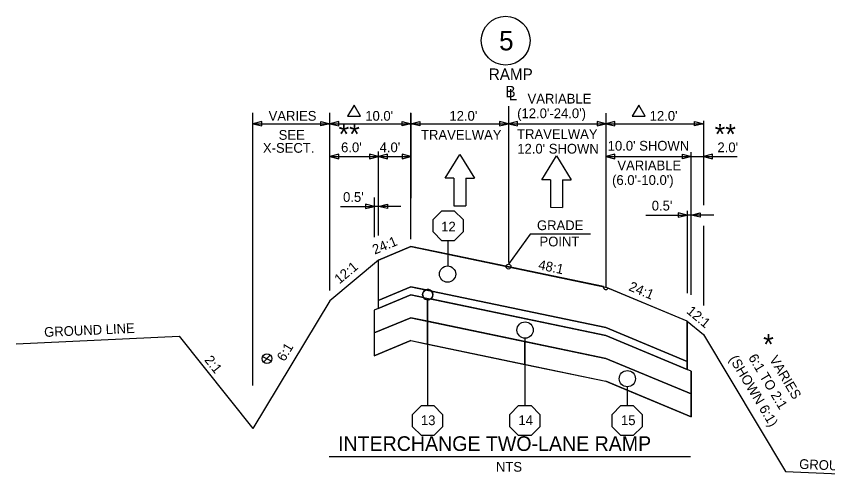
# Model space of a CAD drawing. Extents: x 4932 to 5887, y 4809 to 5473.
# Drawn here: x 5128.5 to 5228.3, y 4886.7 to 4943.3 of the extents above; entities that cross this region are included whole.
import ezdxf

# ---------------------------------------------------------------- set-up
doc = ezdxf.new("R2010")
doc.units = 0
for name, color, linetype in [('Level 2', 7, 'Continuous'), ('Level 20', 7, 'Continuous'), ('Level 25', 7, 'Continuous'), ('RD_QTY_Miscl_1', 7, 'Continuous'), ('RD_QTY_Miscl_2', 7, 'Continuous'), ('RD_QTY_Miscl_3', 7, 'Continuous'), ('RD_QTY_Miscl_4', 7, 'Continuous'), ('RD_SHT_Typical', 7, 'Continuous'), ('RD_TX_TypSect', 7, 'Continuous'), ('RD_XS_ExGround', 7, 'Continuous'), ('typical_on', 7, 'Continuous')]:
    doc.layers.add(name, color=color, linetype=linetype)

msp = doc.modelspace()

# ---------------------------------------------------------------- linework, layer by layer
at = {"layer": 'Level 2'}
for p, q in [((5173.043, 4910.319), (5173.043, 4910.319)), ((5173.043, 4910.264), (5173.043, 4910.264))]:
    msp.add_line(p, q, dxfattribs=at)
at = {"layer": 'Level 20'}
for p, q in [((5181.259, 4923.398), (5183.081, 4926.313)), ((5183.081, 4926.313), (5184.865, 4923.389)), ((5193.153, 4923.198), (5194.975, 4926.112)), ((5194.975, 4926.112), (5196.759, 4923.188)), ((5182.352, 4923.398), (5181.259, 4923.398)), ((5182.352, 4923.398), (5182.352, 4919.997)), ((5183.808, 4923.389), (5184.865, 4923.389)), ((5183.808, 4923.389), (5183.808, 4919.989)), ((5194.245, 4923.198), (5193.153, 4923.198)), ((5194.245, 4923.198), (5194.245, 4919.797)), ((5195.702, 4923.188), (5196.759, 4923.188)), ((5195.702, 4923.188), (5195.702, 4919.788)), ((5182.352, 4919.997), (5183.808, 4919.989)), ((5194.245, 4919.797), (5195.702, 4919.788))]:
    msp.add_line(p, q, dxfattribs=at)
at = {"layer": 'Level 25'}
for p, q in [((5191.736, 4916.499), (5189.068, 4912.805)), ((5199.132, 4916.499), (5191.736, 4916.499))]:
    msp.add_line(p, q, dxfattribs=at)
msp.add_circle((5188.709, 4940.304), 3, dxfattribs=at)
at = {"layer": 'RD_QTY_Miscl_1'}
for p, q in [((5177.064, 4914.978), (5173.065, 4913.312)), ((5173.043, 4913.293), (5173.043, 4908.338)), ((5173.043, 4908.338), (5177.064, 4910.013)), ((5177.064, 4910.013), (5178.885, 4909.634)), ((5211.051, 4905.801), (5201.325, 4909.853)), ((5179.587, 4909.488), (5201.054, 4905.015)), ((5211.052, 4900.85), (5211.051, 4905.801)), ((5201.054, 4905.015), (5211.052, 4900.85))]:
    msp.add_line(p, q, dxfattribs=at)
for points in [[(5200.759, 4910.042), (5181.633, 4914.026), (5177.064, 4914.978)], [(5173.065, 4913.312), (5173.048, 4913.297), (5173.043, 4913.293)]]:
    msp.add_lwpolyline(points, dxfattribs=at)
msp.add_circle((5181.563, 4911.58), 1, dxfattribs=at)
for centre, radius, start, end in [((5201.053, 4909.98), 0.3, 168.23191, 334.96624), ((5179.13, 4909.054), 0.63, 43.52941, 112.93441)]:
    msp.add_arc(centre, radius, start, end, dxfattribs=at)
at = {"layer": 'RD_QTY_Miscl_2'}
for p, q in [((5177.064, 4910.013), (5173.043, 4908.338)), ((5178.885, 4909.634), (5177.064, 4910.013)), ((5173.043, 4907.364), (5177.036, 4909.027)), ((5177.036, 4909.027), (5178.61, 4908.7)), ((5201.054, 4905.015), (5179.587, 4909.488)), ((5173.043, 4908.338), (5173.043, 4907.364)), ((5179.466, 4908.521), (5201.053, 4904.024)), ((5211.052, 4900.85), (5201.054, 4905.015)), ((5201.053, 4904.024), (5211.052, 4899.858))]:
    msp.add_line(p, q, dxfattribs=at)
msp.add_lwpolyline([(5211.052, 4899.858), (5211.052, 4900.85), (5211.052, 4900.85)], dxfattribs=at)
for start, end in [(112.93441, 214.27963), (302.18419, 43.52941)]:
    msp.add_arc((5179.13, 4909.054), 0.63, start, end, dxfattribs=at)
at = {"layer": 'RD_QTY_Miscl_3'}
for p, q in [((5177.036, 4909.027), (5173.043, 4907.364)), ((5178.61, 4908.7), (5177.036, 4909.027)), ((5179.111, 4908.425), (5179.111, 4905.784)), ((5179.111, 4905.784), (5179.111, 4908.425)), ((5201.053, 4904.024), (5179.466, 4908.521)), ((5173.043, 4907.364), (5172.543, 4907.155)), ((5172.543, 4907.155), (5172.543, 4904.344)), ((5172.543, 4904.344), (5177.036, 4906.216)), ((5177.036, 4906.216), (5179.111, 4905.784)), ((5201.053, 4901.213), (5211.55, 4896.839)), ((5211.55, 4896.839), (5211.55, 4899.65))]:
    msp.add_line(p, q, dxfattribs=at)
for points in [[(5179.111, 4905.784), (5191.069, 4903.293), (5201.053, 4901.213)], [(5211.55, 4899.65), (5211.052, 4899.858), (5201.053, 4904.024)]]:
    msp.add_lwpolyline(points, dxfattribs=at)
msp.add_circle((5191.106, 4904.698), 1, dxfattribs=at)
for start, end in [(214.27963, 268.26918), (268.26918, 302.18419)]:
    msp.add_arc((5179.13, 4909.054), 0.63, start, end, dxfattribs=at)
at = {"layer": 'RD_QTY_Miscl_4'}
for p, q in [((5177.036, 4906.216), (5172.543, 4904.344)), ((5179.111, 4905.784), (5177.036, 4906.216)), ((5179.111, 4902.973), (5179.111, 4905.784)), ((5191.069, 4903.293), (5179.111, 4905.784)), ((5179.111, 4905.784), (5179.111, 4902.973)), ((5172.543, 4901.533), (5177.036, 4903.405)), ((5177.036, 4903.405), (5179.111, 4902.973)), ((5179.111, 4902.973), (5191.069, 4900.482)), ((5191.069, 4900.482), (5191.069, 4903.293)), ((5201.053, 4901.213), (5191.069, 4903.293)), ((5191.069, 4903.293), (5191.069, 4900.482)), ((5211.55, 4896.839), (5201.053, 4901.213)), ((5191.069, 4900.482), (5201.053, 4898.402)), ((5211.55, 4894.028), (5211.55, 4896.839))]:
    msp.add_line(p, q, dxfattribs=at)
for points in [[(5172.543, 4904.344), (5172.543, 4904.342), (5172.543, 4901.533)], [(5201.053, 4898.402), (5203.643, 4897.323), (5211.55, 4894.028)]]:
    msp.add_lwpolyline(points, dxfattribs=at)
msp.add_circle((5203.682, 4898.719), 1, dxfattribs=at)
at = {"layer": 'RD_SHT_Typical'}
for p, q in [((5173.065, 4913.312), (5177.064, 4914.978)), ((5173.065, 4913.312), (5167.068, 4908.314)), ((5173.043, 4913.303), (5173.043, 4907.364)), ((5173.043, 4908.338), (5177.064, 4910.013)), ((5211.051, 4905.801), (5200.987, 4909.994)), ((5177.036, 4909.027), (5172.538, 4907.153)), ((5177.036, 4909.027), (5201.053, 4904.024)), ((5167.068, 4908.314), (5157.624, 4892.575)), ((5172.543, 4907.155), (5172.543, 4901.533)), ((5177.036, 4906.216), (5172.538, 4904.342)), ((5177.036, 4906.216), (5201.053, 4901.213)), ((5211.051, 4905.801), (5213.05, 4904.135)), ((5211.052, 4905.8), (5211.052, 4899.858)), ((5211.052, 4900.85), (5201.054, 4905.015)), ((5148.539, 4903.931), (5157.624, 4892.575)), ((5211.55, 4899.65), (5201.053, 4904.024)), ((5213.05, 4904.135), (5223.152, 4887.297)), ((5177.036, 4903.405), (5172.543, 4901.533)), ((5177.036, 4903.405), (5201.053, 4898.402)), ((5211.55, 4896.839), (5201.053, 4901.213)), ((5211.55, 4899.65), (5211.55, 4894.028)), ((5211.55, 4894.028), (5201.053, 4898.402))]:
    msp.add_line(p, q, dxfattribs=at)
for points in [[(5177.064, 4914.978), (5200.987, 4909.994)], [(5177.064, 4910.013), (5201.054, 4905.015)]]:
    msp.add_lwpolyline(points, dxfattribs=at)
at = {"layer": 'RD_TX_TypSect'}
for p, q in [((5189.06, 4932.248), (5189.06, 4913.03)), ((5157.624, 4897.859), (5157.624, 4931.411)), ((5167.068, 4909.562), (5167.068, 4931.411)), ((5177.064, 4915.894), (5177.064, 4931.411)), ((5177.064, 4931.376), (5177.064, 4920.915)), ((5201.054, 4931.376), (5201.054, 4909.98)), ((5157.624, 4930.086), (5167.068, 4930.086)), ((5167.068, 4930.086), (5177.064, 4930.086)), ((5177.064, 4930.086), (5189.06, 4930.086)), ((5189.06, 4930.086), (5201.054, 4930.086)), ((5201.054, 4930.086), (5213.048, 4930.086)), ((5213.048, 4930.426), (5213.048, 4920.254)), ((5167.068, 4926.048), (5173.065, 4926.048)), ((5173.065, 4916.346), (5173.065, 4926.667)), ((5173.065, 4926.048), (5177.064, 4926.048)), ((5201.054, 4926.048), (5211.049, 4926.048)), ((5211.049, 4926.048), (5213.048, 4926.048)), ((5211.55, 4909.025), (5211.55, 4926.583)), ((5213.048, 4926.048), (5217.188, 4926.048)), ((5172.566, 4916.12), (5172.566, 4920.99)), ((5168.385, 4919.91), (5172.566, 4919.91)), ((5175.831, 4919.91), (5172.566, 4919.91)), ((5213.051, 4920.237), (5213.051, 4920.068)), ((5205.959, 4918.846), (5211.049, 4918.846)), ((5211.052, 4919.38), (5211.052, 4909.233)), ((5214.314, 4918.846), (5211.052, 4918.846)), ((5213.05, 4917.522), (5213.05, 4907.725)), ((5181.633, 4912.578), (5181.633, 4915.682)), ((5179.111, 4908.425), (5179.111, 4895.411)), ((5191.069, 4903.699), (5191.069, 4895.411)), ((5158.799, 4901.454), (5159.871, 4900.907)), ((5158.922, 4900.762), (5159.748, 4901.605)), ((5203.643, 4897.72), (5203.643, 4895.411)), ((5167.016, 4889.125), (5211.47, 4889.125))]:
    msp.add_line(p, q, dxfattribs=at)
for points in [[(5170.068, 4932.381), (5169.269, 4930.997), (5170.868, 4930.997)], [(5205.076, 4932.381), (5204.276, 4930.997), (5205.875, 4930.997)], [(5158.727, 4929.811), (5158.727, 4930.361), (5157.624, 4930.086)], [(5165.965, 4929.811), (5165.965, 4930.361), (5167.068, 4930.086)], [(5168.17, 4929.811), (5168.17, 4930.361), (5167.068, 4930.086)], [(5175.961, 4929.811), (5175.961, 4930.361), (5177.064, 4930.086)], [(5178.166, 4930.361), (5178.166, 4929.811), (5177.064, 4930.086)], [(5187.956, 4930.361), (5187.956, 4929.811), (5189.059, 4930.086)], [(5190.163, 4929.811), (5190.163, 4930.361), (5189.061, 4930.086)], [(5199.95, 4930.361), (5199.95, 4929.811), (5201.053, 4930.086)], [(5202.157, 4929.811), (5202.157, 4930.361), (5201.054, 4930.086)], [(5211.946, 4929.811), (5211.946, 4930.361), (5213.048, 4930.086)], [(5168.17, 4925.773), (5168.17, 4926.323), (5167.068, 4926.048)], [(5171.963, 4926.323), (5171.963, 4925.773), (5173.065, 4926.048)], [(5174.168, 4925.773), (5174.168, 4926.323), (5173.065, 4926.048)], [(5175.961, 4926.323), (5175.961, 4925.773), (5177.064, 4926.048)], [(5202.157, 4925.773), (5202.157, 4926.323), (5201.054, 4926.048)], [(5210.448, 4925.773), (5210.448, 4926.323), (5211.55, 4926.048)], [(5214.151, 4925.773), (5214.151, 4926.323), (5213.048, 4926.048)], [(5171.463, 4920.185), (5171.463, 4919.636), (5172.566, 4919.91)], [(5174.168, 4920.185), (5174.168, 4919.636), (5173.065, 4919.91)], [(5209.946, 4919.121), (5209.946, 4918.571), (5211.049, 4918.846)], [(5212.651, 4919.121), (5212.651, 4918.571), (5211.549, 4918.846)]]:
    msp.add_lwpolyline(points, close=True, dxfattribs=at)
for centre, radius in [((5189.068, 4912.505), 0.3), ((5181.563, 4911.58), 1), ((5179.13, 4909.054), 0.63), ((5191.106, 4904.698), 1), ((5159.341, 4901.186), 0.6), ((5203.682, 4898.719), 1)]:
    msp.add_circle(centre, radius, dxfattribs=at)
at = {"layer": 'RD_XS_ExGround'}
for p, q in [((5128.505, 4903.018), (5148.539, 4903.931)), ((5223.152, 4887.297), (5237.316, 4886.652))]:
    msp.add_line(p, q, dxfattribs=at)
at = {"layer": 'typical_on'}
for points in [[(5183.479, 4918.294), (5183.479, 4916.764), (5182.398, 4915.682), (5180.868, 4915.682), (5179.786, 4916.764), (5179.786, 4918.294), (5180.868, 4919.375), (5182.398, 4919.375)], [(5180.957, 4894.33), (5180.958, 4892.8), (5179.876, 4891.718), (5178.346, 4891.718), (5177.265, 4892.8), (5177.265, 4894.33), (5178.346, 4895.411), (5179.876, 4895.411)], [(5192.915, 4894.33), (5192.915, 4892.8), (5191.834, 4891.718), (5190.304, 4891.718), (5189.222, 4892.8), (5189.222, 4894.33), (5190.304, 4895.411), (5191.834, 4895.411)], [(5205.489, 4894.33), (5205.489, 4892.8), (5204.407, 4891.718), (5202.878, 4891.718), (5201.796, 4892.8), (5201.796, 4894.33), (5202.878, 4895.411), (5204.407, 4895.411)]]:
    msp.add_lwpolyline(points, close=True, dxfattribs=at)

# ---------------------------------------------------------------- texts
at = {"layer": 'Level 25'}
msp.add_text('5', height=2.4, dxfattribs=at).set_placement((5187.906, 4939.104))
at = {"layer": 'RD_TX_TypSect'}
for s, height, p in [('RAMP', 1.4, (5186.641, 4935.476)), ('B ', 1.4, (5188.688, 4933.338)), ('L', 1.4, (5189.097, 4932.953)), ('VARIES', 1.2, (5159.551, 4930.449)), ("10.0'", 1.2, (5171.444, 4930.449)), ("12.0'", 1.2, (5181.796, 4930.449)), ("12.0'", 1.2, (5206.43, 4930.449)), ('**', 2.5, (5168.16, 4927.559)), ('**', 2.5, (5214.427, 4927.559)), ('SEE', 1.2, (5160.79, 4928.104)), ('TRAVELWAY', 1.2, (5178.301, 4928.117)), ("6.0'", 1.2, (5168.467, 4926.575)), ("4.0'", 1.2, (5173.208, 4926.575)), ("10.0' SHOWN", 1.2, (5201.265, 4926.77)), ("2.0'", 1.2, (5214.765, 4926.575)), ('X-SECT.', 1.2, (5158.854, 4926.507)), ("0.5'", 1.2, (5168.71, 4920.467)), ("0.5'", 1.2, (5206.685, 4919.403)), ('12', 1.2, (5180.782, 4916.823)), ('GRADE', 1.2, (5192.566, 4916.988)), ('POINT', 1.2, (5192.878, 4914.989)), ('*', 2.5, (5220.384, 4901.697)), ('13', 1.2, (5178.287, 4893.004)), ('14', 1.2, (5190.28, 4893.004)), ('15', 1.2, (5202.904, 4893.004)), ('INTERCHANGE TWO-LANE RAMP', 1.8, (5168.094, 4889.831)), ('NTS', 1.2, (5187.519, 4887.274))]:
    msp.add_text(s, height=height, dxfattribs=at).set_placement(p)
for s, rotation, p in [('VARIABLE', 0.00163, (5191.409, 4932.563)), ("(12.0'-24.0')", 0.00163, (5190.131, 4930.763)), ('TRAVELWAY', 0.00163, (5190.121, 4928.206)), ("12.0' SHOWN", 0.00163, (5190.142, 4926.406)), ('VARIABLE', 0.00163, (5202.456, 4924.354)), ("(6.0'-10.0')", 0.00163, (5201.804, 4922.554)), ('24:1', 22.61905, (5172.615, 4913.973)), ('12:1', 39.80557, (5168.265, 4910.306)), ('48:1', 348.23171, (5192.653, 4912.191)), ('24:1', 337.38014, (5203.756, 4909.615)), ('12:1', 320.19386, (5210.875, 4906.863)), ('GROUND LINE', 2.60954, (5131.967, 4903.845)), ('6:1', 59.03624, (5161.508, 4900.746)), ('2:1', 308.65981, (5151.595, 4900.987)), ('(SHOWN 6:1)', 300.96376, (5216.168, 4901.162)), ('6:1 TO 2:1', 300.96376, (5218.523, 4901.318)), ('VARIES', 300.96376, (5221.099, 4901.106)), ('GROUND LINE', 357.39046, (5224.8, 4887.636))]:
    msp.add_text(s, height=1.2, rotation=rotation, dxfattribs=at).set_placement(p)

doc.saveas('drawing.dxf')
